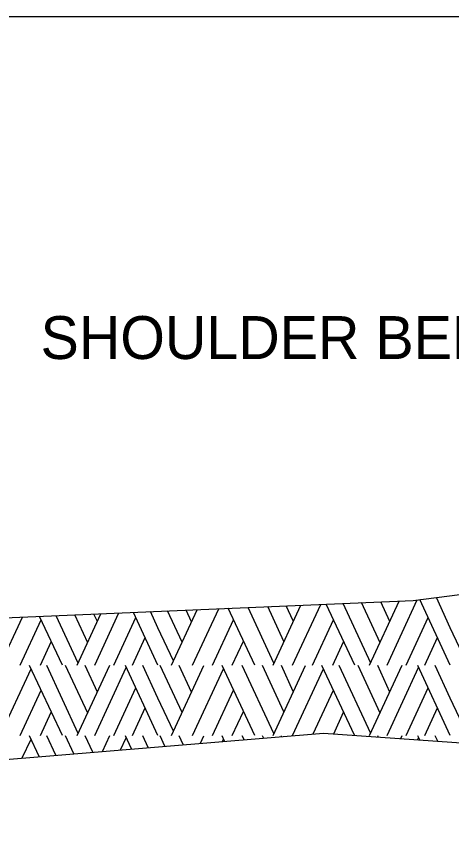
# Model space of a CAD drawing. Extents: x 49991.4 to 50021, y 49987.6 to 50011.4.
# Drawn here: x 50012.738 to 50013.346, y 49989.401 to 49990.562 of the extents above; entities that cross this region are included whole.
import ezdxf

# ---------------------------------------------------------------- set-up
doc = ezdxf.new("R2010")
doc.units = 0
doc.layers.add('Level 1', color=7, linetype='Continuous')
doc.layers.add('Level 2', color=7, linetype='Continuous')

msp = doc.modelspace()

# ---------------------------------------------------------------- linework, layer by layer
at = {"layer": 'Level 1'}
for p, q in [((49999.3835, 49990.5622), (50016.7501, 49990.5622)), ((50013.2328, 49989.6579), (50013.1941, 49989.7412)), ((50013.2459, 49989.6862), (50013.22, 49989.7424)), ((50013.2313, 49989.6548), (50013.2727, 49989.7446)), ((50013.2597, 49989.7158), (50013.2469, 49989.7435)), ((50013.2557, 49989.6548), (50013.2978, 49989.7461)), ((50013.3441, 49989.6548), (50013.3016, 49989.7466)), ((50013.3441, 49989.7072), (50013.3246, 49989.7496)), ((50012.9353, 49989.7072), (50012.925, 49989.7298)), ((50012.9692, 49989.6871), (50012.9488, 49989.7308)), ((50012.9542, 49989.6548), (50012.9902, 49989.7325)), ((50012.9823, 49989.7155), (50012.9748, 49989.7319)), ((50012.9835, 49989.6548), (50013.0203, 49989.7338)), ((50013.0707, 49989.6548), (50013.0336, 49989.7344)), ((50013.0975, 49989.6576), (50013.0614, 49989.7356)), ((50013.1115, 49989.688), (50013.0891, 49989.7368)), ((50013.0963, 49989.6548), (50013.1351, 49989.7387)), ((50013.1243, 49989.7167), (50013.1147, 49989.7379)), ((50013.1234, 49989.6548), (50013.1629, 49989.7399)), ((50013.2106, 49989.6548), (50013.1705, 49989.7402)), ((50012.7147, 49989.6548), (50012.7459, 49989.7221)), ((50012.7427, 49989.6548), (50012.772, 49989.7185)), ((50012.8018, 49989.6548), (50012.7698, 49989.7231)), ((50012.8241, 49989.6579), (50012.7933, 49989.7241)), ((50012.8372, 49989.6862), (50012.8192, 49989.7253)), ((50012.8226, 49989.6548), (50012.8558, 49989.7268)), ((50012.8509, 49989.7158), (50012.846, 49989.7264)), ((50012.847, 49989.6548), (50012.8807, 49989.7279)), ((50012.8738, 49989.6548), (50012.9043, 49989.7216)), ((50012.9353, 49989.6548), (50012.9011, 49989.7287)), ((50013.0115, 49989.6548), (50013.0411, 49989.7185)), ((50013.1515, 49989.6548), (50013.1807, 49989.7185)), ((50013.2825, 49989.6548), (50013.313, 49989.7216)), ((50012.957, 49989.6609), (50012.9353, 49989.7072)), ((50013.3657, 49989.6609), (50013.3441, 49989.7072)), ((50012.7714, 49989.6548), (50012.7863, 49989.6877)), ((50012.8997, 49989.6548), (50012.9174, 49989.6935)), ((50013.0393, 49989.6548), (50013.0548, 49989.6886)), ((50013.1801, 49989.6548), (50013.195, 49989.6877)), ((50013.3084, 49989.6548), (50013.3261, 49989.6935)), ((50012.7147, 49989.5564), (50012.758, 49989.6496)), ((50012.8018, 49989.5564), (50012.7558, 49989.6545)), ((50012.8241, 49989.5594), (50012.7799, 49989.6545)), ((50012.8372, 49989.5878), (50012.8064, 49989.6545)), ((50012.8226, 49989.5564), (50012.868, 49989.6548)), ((50012.8509, 49989.6173), (50012.8338, 49989.6545)), ((50012.847, 49989.5564), (50012.8908, 49989.6515)), ((50012.9353, 49989.5564), (50012.8899, 49989.6545)), ((50012.9353, 49989.6088), (50012.9143, 49989.6545)), ((50012.9692, 49989.5887), (50012.9384, 49989.6545)), ((50012.9542, 49989.5564), (50012.9997, 49989.6545)), ((50012.9823, 49989.617), (50012.9652, 49989.6545)), ((50012.9835, 49989.5564), (50013.0271, 49989.6499)), ((50013.0707, 49989.5564), (50013.025, 49989.6545)), ((50013.0975, 49989.5591), (50013.0533, 49989.6545)), ((50013.1115, 49989.5896), (50013.0817, 49989.6545)), ((50013.0963, 49989.5564), (50013.1417, 49989.6545)), ((50013.1243, 49989.6182), (50013.1079, 49989.6545)), ((50013.1234, 49989.5564), (50013.1667, 49989.6496)), ((50013.2104, 49989.5568), (50013.1646, 49989.6545)), ((50013.2328, 49989.5594), (50013.1886, 49989.6545)), ((50013.2459, 49989.5878), (50013.2152, 49989.6545)), ((50013.2313, 49989.5564), (50013.2767, 49989.6548)), ((50013.2597, 49989.6173), (50013.2426, 49989.6545)), ((50013.2557, 49989.5564), (50013.2996, 49989.6515)), ((50013.3441, 49989.5564), (50013.2987, 49989.6545)), ((50013.3441, 49989.6088), (50013.3231, 49989.6545)), ((50012.7427, 49989.5564), (50012.772, 49989.6201)), ((50012.8738, 49989.5564), (50012.9043, 49989.6231)), ((50013.0115, 49989.5564), (50013.0411, 49989.6201)), ((50013.1525, 49989.5587), (50013.1807, 49989.6201)), ((50013.2825, 49989.5564), (50013.313, 49989.6231)), ((50012.957, 49989.5625), (50012.9353, 49989.6088)), ((50013.3657, 49989.5625), (50013.3441, 49989.6088)), ((50012.8997, 49989.5564), (50012.9174, 49989.5951)), ((50013.0393, 49989.5564), (50013.0548, 49989.5902)), ((50013.3084, 49989.5564), (50013.3261, 49989.5951)), ((50012.7714, 49989.5564), (50012.7863, 49989.5893)), ((50013.1812, 49989.5589), (50013.195, 49989.5893)), ((50012.5876, 49989.512), (50013.1668, 49989.5599)), ((50012.7694, 49989.527), (50012.7558, 49989.5561)), ((50012.7925, 49989.5289), (50012.7799, 49989.5561)), ((50012.818, 49989.531), (50012.8064, 49989.5561)), ((50012.8443, 49989.5332), (50012.8338, 49989.5561)), ((50012.8578, 49989.5343), (50012.868, 49989.5564)), ((50012.8984, 49989.5377), (50012.8899, 49989.5561)), ((50012.9219, 49989.5396), (50012.9143, 49989.5561)), ((50012.9452, 49989.5416), (50012.9384, 49989.5561)), ((50012.9708, 49989.5437), (50012.9652, 49989.5561)), ((50012.9949, 49989.5457), (50012.9997, 49989.5561)), ((50013.0285, 49989.5485), (50013.025, 49989.5561)), ((50013.0558, 49989.5507), (50013.0533, 49989.5561)), ((50013.0831, 49989.553), (50013.0817, 49989.5561)), ((50013.1083, 49989.5551), (50013.1079, 49989.5561)), ((50013.1668, 49989.5599), (50013.6545, 49989.525)), ((50013.2433, 49989.5544), (50013.2426, 49989.5561)), ((50013.2748, 49989.5522), (50013.2767, 49989.5564)), ((50013.3013, 49989.5503), (50013.2987, 49989.5561)), ((50013.3265, 49989.5485), (50013.3231, 49989.5561)), ((50012.7458, 49989.5251), (50012.758, 49989.5512)), ((50012.8832, 49989.5364), (50012.8908, 49989.553)), ((50013.0256, 49989.5482), (50013.0271, 49989.5515)), ((50013.2984, 49989.5505), (50013.2996, 49989.553))]:
    msp.add_line(p, q, dxfattribs=at)
msp.add_lwpolyline([(50011.0447, 49989.4013), (50011.8025, 49989.7802), (50011.9613, 49989.891), (50012.0991, 49989.964), (50012.2318, 49989.9732), (50012.3828, 49989.9091), (50012.4676, 49989.8447), (50012.5525, 49989.7802), (50012.643, 49989.7177), (50013.2924, 49989.7454), (50013.5638, 49989.7802), (50014.0674, 49989.7802)], dxfattribs=at)

# ---------------------------------------------------------------- texts
at = {"layer": 'Level 2'}
msp.add_text('SHOULDER BERM', height=0.06, dxfattribs=at).set_placement((50012.7713, 49990.0832))

doc.saveas('drawing.dxf')
